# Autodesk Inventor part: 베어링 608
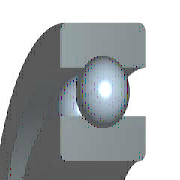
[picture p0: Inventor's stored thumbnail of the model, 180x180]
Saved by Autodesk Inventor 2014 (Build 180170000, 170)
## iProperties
IsCustomPart: 1
Created: 2009-02
Part Number: 베어링 608
Material: 강, 연강
Description: 깊은 그루브 볼 베어링
Document SubType Name: Modeling
Standard: KS B 2023
Designer: 한국산업디자인학원
Standards Organization: KS
Language: ko-KR
Size Designation: 608 - 8 x 22 x 7
Categories: <MemberInstance><Categories><Category DisplayName="샤프트 부품" InternalName="7f7aeb1f-a693-4053-b835-cee3144e0d98" Mnemonic="SHFT"><Category DisplayName="베어링" Inter
Density: 1 g/cm^3
Appearance: 강철
Author: 한국산업디자인학원
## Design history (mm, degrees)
sketch "스케치" dims "d0" = 3.64 (= -0.26 x WD + 0.26 x BD)
  geometry: L1 (1.68, 7.5)-(5.32, 7.5); L2 (3.5, 7.5)-(3.5, 5.68); L3 (3.5, 7.5)-(3.5, 9.32); L4 (2.148, 6.282)-(0, 6.282); L5 (0, 4)-(7, 4); L6 (2.148, 8.718)-(0, 8.718); L7 (0, 11)-(7, 11); L8 (7, 4)-(7, 6.282); L9 (4.852, 6.282)-(7, 6.282); L10 (4.852, 8.718)-(7, 8.718); L11 (7, 11)-(7, 8.718); L12 (-1.4, 0)-(8.4, 0) reference; L13 (0, -0.3)-(0, 5.3) reference
  constraints: 22 end point, 4 point on line, 2 collinear, 2 perpendicular, 2 symmetric about line, 1 midpoint, 1 parallel, 14 other
  dimensions: "d9" = 8 diameter of L5 L12 (= WD); "d11" = 22 diameter of L7 L12 (= BD); "d12" = 7 distance between parallel lines of L8 L13 (= KB); "d13" = 12.564 diameter of L9 L12 (= 0.326 x BD + 0.674 x WD)
revolve "본체" stored, may be unused: angle "d6" = 90 deg
revolve "볼" stored, may be unused: angle "d7" = 90 deg
pattern_circular "IDS_ARRAYBALL[SIMPL:T]" dims angle "d3" = 360 deg
body "Solid1"
fillet "모깎기1" dims "d1" = 0.3 (= KRS)
other parameters: "WD" = 8 [user parameter; used in 5 equation terms], "BD" = 22 [user parameter; used in 5 equation terms], "KB" = 7 [user parameter; used in 1 equation term], "KRS" = 0.3 [user parameter; used in 1 equation term], "d4" = 0, "d5" = 0, "d8" = 0, "d14" = 0, "d15" = 0, "BBA" = 0 [user parameter], "BC0" = 1370000 [user parameter], "BC" = 3250000 [user parameter], "BR" = 11 (= 0.5 x BD) [user parameter], "WR" = 4 (= 0.5 x WD) [user parameter]
